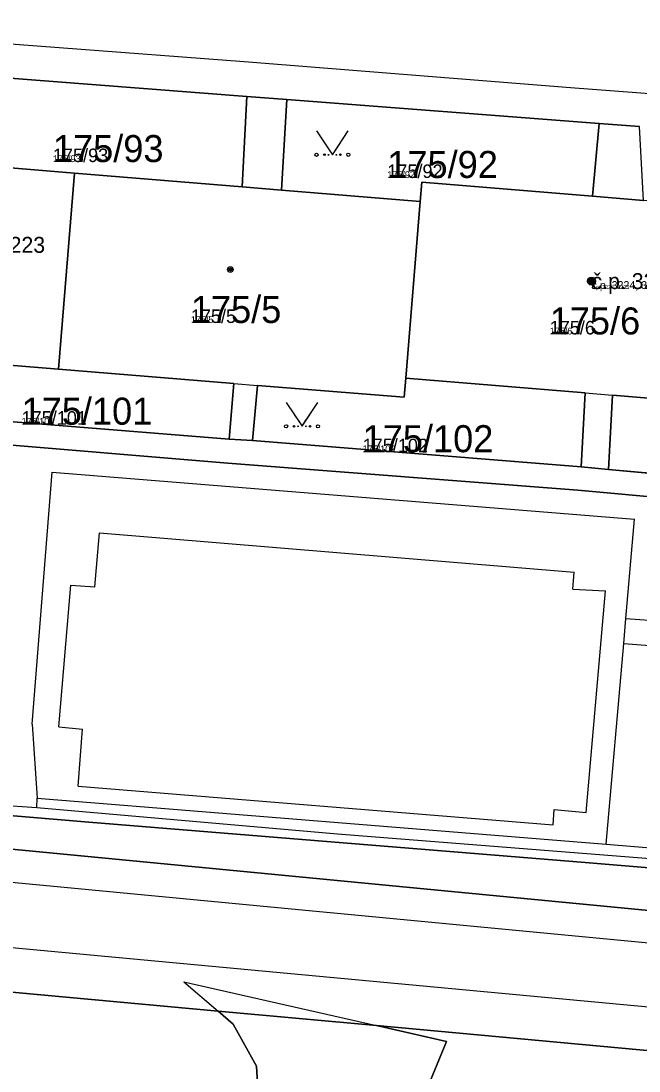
# Model space of a CAD drawing. Extents: x -759873 to -758487, y -975024 to -973516.
# Drawn here: x -759644.6 to -759605.8, y -974770.4 to -974704.4 of the extents above; entities that cross this region are included whole.
import ezdxf

# ---------------------------------------------------------------- set-up
doc = ezdxf.new("R2010")
doc.units = 0
for name, color, linetype in [('KAT_02_hranice parcel', 7, 'Continuous'), ('KAT_03_1000_st čísla parcelní', 7, 'Continuous'), ('KAT_03_1000_čísla parcelní', 7, 'Continuous'), ('KAT_03_1000_čísla popisná', 7, 'Continuous'), ('KAT_03_250_st čísla parcelní', 7, 'Continuous'), ('KAT_03_250_čísla parcelní', 7, 'Continuous'), ('KAT_03_250_čísla popisná', 7, 'Continuous'), ('KAT_03_500_st čísla parcelní', 7, 'Continuous'), ('KAT_03_500_čísla parcelní', 7, 'Continuous'), ('KAT_03_500_čísla popisná', 7, 'Continuous'), ('KAT_04_vnitřní kresba', 7, 'Continuous'), ('KAT_05_1000_značky kultur', 7, 'Continuous'), ('KAT_05_250_značky kultur', 7, 'Continuous'), ('KAT_05_500_značky kultur', 7, 'Continuous'), ('KAT_07_1000_značky budov', 7, 'Continuous'), ('KAT_07_250_značky budov', 7, 'Continuous'), ('KAT_07_500_značky budov', 7, 'Continuous'), ('KAT_14_plocha_budovy', 7, 'Continuous'), ('KAT_14_plocha_pozemek', 7, 'Continuous')]:
    doc.layers.add(name, color=color, linetype=linetype)

msp = doc.modelspace()

# ---------------------------------------------------------------- linework, layer by layer
at = {"layer": 'KAT_02_hranice parcel'}
for p, q in [((-759649.39, -974707.68), (-759630.43, -974709.14)), ((-759627.92, -974709.32), (-759630.43, -974709.14)), ((-759627.92, -974709.32), (-759608.29, -974710.84)), ((-759605.74, -974711.03), (-759608.29, -974710.84)), ((-759642.27, -974726.27), (-759641.27, -974713.96)), ((-759620.43, -974726.84), (-759619.53, -974715.73)), ((-759651.64, -974729.05), (-759631.54, -974730.66)), ((-759631.54, -974730.66), (-759630.08, -974730.75)), ((-759630.08, -974730.75), (-759609.42, -974732.4)), ((-759609.42, -974732.4), (-759607.69, -974732.58)), ((-759607.69, -974732.58), (-759588.03, -974734.34)), ((-759622.27, -974767.52), (-759632.24, -974766.61))]:
    msp.add_line(p, q, dxfattribs=at)
for points in [[(-759641.27, -974713.96), (-759649.11, -974713.31), (-759649.39, -974707.68)], [(-759630.43, -974709.14), (-759630.73, -974714.82), (-759641.27, -974713.96)], [(-759619.53, -974715.73), (-759628.26, -974715.02), (-759627.92, -974709.32)], [(-759608.29, -974710.84), (-759608.7, -974715.41), (-759619.43, -974714.53), (-759619.53, -974715.73)], [(-759651.64, -974729.05), (-759651.25, -974725.53), (-759642.27, -974726.27)], [(-759642.27, -974726.27), (-759631.25, -974727.17), (-759631.54, -974730.66)], [(-759630.08, -974730.75), (-759629.76, -974727.29), (-759620.53, -974728.04), (-759620.43, -974726.84)], [(-759620.43, -974726.84), (-759609.16, -974727.76), (-759609.42, -974732.4)], [(-759607.69, -974732.58), (-759607.44, -974727.9), (-759598.63, -974728.63)], [(-759647.22, -974730.88), (-759631.63, -974732.18), (-759609.62, -974733.88), (-759603.65, -974734.41), (-759602.12, -974734.54), (-759585.63, -974736), (-759581.26, -974735.71)], [(-759632.24, -974766.61), (-759693, -974761.02), (-759748.53, -974752.57), (-759765.29, -974749.94), (-759777.22, -974746.13)], [(-759717.74, -974748.2), (-759711.27, -974749.14), (-759692.25, -974751.9), (-759582.09, -974762.5), (-759499.92, -974767.02), (-759477.49, -974765.76)], [(-759560.6, -974761.29), (-759572.03, -974760.36), (-759609.16, -974757.26), (-759640.37, -974754.73), (-759646.11, -974754.26), (-759649.25, -974754), (-759649.17, -974753.04)], [(-759709.76, -974789.79), (-759694.52, -974791.11), (-759689.46, -974791.19), (-759651.79, -974790.02), (-759639.49, -974789.57), (-759635.49, -974788.88), (-759632.45, -974786.48), (-759630.15, -974781.17), (-759629.53, -974775.06), (-759629.82, -974770.06), (-759631.29, -974767.42), (-759632.24, -974766.61)], [(-759493.33, -974775.87), (-759498.32, -974775.83), (-759582.59, -974771.17), (-759622.27, -974767.52)], [(-759610.35, -974777.27), (-759613.56, -974776.84), (-759617.11, -974774.92), (-759619.06, -974771.36), (-759617.87, -974768.52), (-759622.27, -974767.52)]]:
    msp.add_lwpolyline(points, dxfattribs=at)
at = {"layer": 'KAT_03_1000_čísla popisná'}
msp.add_circle((-759608.76, -974720.74), 0.25, dxfattribs=at)
at = {"layer": 'KAT_03_250_čísla popisná'}
msp.add_circle((-759608.76, -974720.74), 0.0625, dxfattribs=at)
at = {"layer": 'KAT_03_500_čísla popisná'}
msp.add_circle((-759608.76, -974720.74), 0.125, dxfattribs=at)
at = {"layer": 'KAT_04_vnitřní kresba'}
for p, q in [((-759653.32, -974705.22), (-759630.6, -974706.95)), ((-759630.6, -974706.95), (-759610.08, -974708.57)), ((-759610.08, -974708.57), (-759591.35, -974710.02)), ((-759630.73, -974714.82), (-759628.26, -974715.02)), ((-759608.7, -974715.41), (-759605.49, -974715.67)), ((-759631.25, -974727.17), (-759629.76, -974727.29)), ((-759609.16, -974727.76), (-759607.44, -974727.9)), ((-759643.93, -974748.57), (-759642.67, -974732.75)), ((-759642.67, -974732.75), (-759606.05, -974735.69)), ((-759606.6, -974741.93), (-759606.05, -974735.69)), ((-759639.99, -974739.95), (-759639.7, -974736.55)), ((-759639.7, -974736.55), (-759609.85, -974739.03)), ((-759609.94, -974740.09), (-759609.85, -974739.03)), ((-759642.25, -974748.74), (-759641.5, -974739.85)), ((-759641.5, -974739.85), (-759639.99, -974739.95)), ((-759609.94, -974740.09), (-759607.89, -974740.2)), ((-759609.09, -974754.13), (-759607.89, -974740.2)), ((-759606.74, -974743.5), (-759606.6, -974741.93)), ((-759606.6, -974741.93), (-759604.26, -974742.11)), ((-759607.85, -974756.12), (-759606.74, -974743.5)), ((-759606.74, -974743.5), (-759604.06, -974743.71)), ((-759643.93, -974748.57), (-759643.6, -974753.23)), ((-759642.25, -974748.74), (-759640.75, -974748.9)), ((-759641.04, -974752.48), (-759640.75, -974748.9)), ((-759641.04, -974752.48), (-759611.18, -974754.91)), ((-759646.1, -974753.65), (-759643.64, -974753.81)), ((-759643.64, -974753.81), (-759643.6, -974753.23)), ((-759643.6, -974753.23), (-759607.85, -974756.12)), ((-759692.41, -974754), (-759582.2, -974764.5)), ((-759643.64, -974753.81), (-759624.72, -974755.47)), ((-759611.18, -974754.91), (-759611.1, -974753.94)), ((-759611.1, -974753.94), (-759609.09, -974754.13)), ((-759624.72, -974755.47), (-759588.82, -974758.29)), ((-759607.85, -974756.12), (-759560.5, -974759.95)), ((-759692.8, -974758.18), (-759582.51, -974768.44)), ((-759634.38, -974764.77), (-759632.24, -974766.61)), ((-759634.38, -974764.77), (-759622.27, -974767.52))]:
    msp.add_line(p, q, dxfattribs=at)
at = {"layer": 'KAT_05_1000_značky kultur'}
for points in [[(-759626.05, -974711.299), (-759625.05, -974712.8), (-759624.05, -974711.299)], [(-759627.96, -974728.359), (-759626.96, -974729.86), (-759625.96, -974728.359)]]:
    msp.add_lwpolyline(points, dxfattribs=at)
for centre in [(-759626.05, -974712.799), (-759624.05, -974712.799), (-759627.96, -974729.859), (-759625.96, -974729.859)]:
    msp.add_circle(centre, 0.1, dxfattribs=at)
at = {"layer": 'KAT_05_250_značky kultur'}
for points in [[(-759625.3, -974712.425), (-759625.05, -974712.8), (-759624.8, -974712.425)], [(-759627.21, -974729.485), (-759626.96, -974729.86), (-759626.71, -974729.485)]]:
    msp.add_lwpolyline(points, dxfattribs=at)
for centre in [(-759625.3, -974712.8), (-759624.8, -974712.8), (-759627.21, -974729.86), (-759626.71, -974729.86)]:
    msp.add_circle(centre, 0.025, dxfattribs=at)
at = {"layer": 'KAT_05_500_značky kultur'}
for points in [[(-759625.55, -974712.049), (-759625.05, -974712.8), (-759624.55, -974712.049)], [(-759627.46, -974729.11), (-759626.96, -974729.86), (-759626.46, -974729.11)]]:
    msp.add_lwpolyline(points, dxfattribs=at)
for centre in [(-759625.55, -974712.8), (-759624.55, -974712.8), (-759627.46, -974729.86), (-759626.46, -974729.86)]:
    msp.add_circle(centre, 0.05, dxfattribs=at)
at = {"layer": 'KAT_07_1000_značky budov'}
for centre in [(-759631.467, -974720.009), (-759608.767, -974720.739)]:
    msp.add_circle(centre, 0.175, dxfattribs=at)
at = {"layer": 'KAT_07_250_značky budov'}
for centre in [(-759631.462, -974720.01), (-759608.762, -974720.74)]:
    msp.add_circle(centre, 0.0437, dxfattribs=at)
at = {"layer": 'KAT_07_500_značky budov'}
for centre in [(-759631.463, -974720.01), (-759608.763, -974720.74)]:
    msp.add_circle(centre, 0.0875, dxfattribs=at)
at = {"layer": 'KAT_14_plocha_budovy'}
for points in [[(-759663.01, -974712.18), (-759664.01, -974724.49), (-759652.77, -974725.41), (-759651.25, -974725.53), (-759642.27, -974726.27), (-759631.25, -974727.17), (-759629.76, -974727.29), (-759620.53, -974728.04), (-759620.43, -974726.84), (-759619.53, -974715.73), (-759628.26, -974715.02), (-759630.73, -974714.82), (-759641.27, -974713.96), (-759649.11, -974713.31), (-759652.31, -974713.05)], [(-759620.43, -974726.84), (-759609.16, -974727.76), (-759607.44, -974727.9), (-759598.63, -974728.63), (-759587.58, -974729.53), (-759585.9, -974729.67), (-759576.84, -974730.41), (-759575.83, -974718.1), (-759584.58, -974717.38), (-759587.06, -974717.18), (-759597.63, -974716.32), (-759605.49, -974715.67), (-759608.7, -974715.41), (-759619.43, -974714.53), (-759619.53, -974715.73)]]:
    msp.add_lwpolyline(points, close=True, dxfattribs=at)
at = {"layer": 'KAT_14_plocha_pozemek'}
for points in [[(-759721.85, -974701.93), (-759712.7, -974702.91), (-759710.75, -974703.04), (-759695.32, -974704.11), (-759692.69, -974704.49), (-759673.78, -974705.9), (-759671.39, -974706.09), (-759651.83, -974707.5), (-759649.39, -974707.68), (-759630.43, -974709.14), (-759627.92, -974709.32), (-759608.29, -974710.84), (-759605.74, -974711.03)], [(-759588.03, -974734.34), (-759607.69, -974732.58), (-759609.42, -974732.4), (-759630.08, -974730.75), (-759631.54, -974730.66), (-759651.64, -974729.05), (-759653.14, -974728.9), (-759673.58, -974727.24), (-759675.02, -974727.09), (-759695.14, -974725.4), (-759696.95, -974725.28), (-759712.53, -974723.97), (-759710.75, -974703.04), (-759712.7, -974702.91), (-759713.04, -974706.66), (-759713.31, -974710.06), (-759713.45, -974711.78), (-759713.54, -974712.85), (-759714.48, -974723.81), (-759721.48, -974723.21)], [(-759721.81, -974724.63), (-759713.66, -974725.35), (-759696.72, -974726.85), (-759675.13, -974728.61), (-759653.29, -974730.38), (-759647.22, -974730.88), (-759631.63, -974732.18), (-759609.62, -974733.88), (-759603.65, -974734.41)], [(-759582.09, -974762.5), (-759692.25, -974751.9), (-759711.27, -974749.14), (-759717.74, -974748.2), (-759718.05, -974748.17), (-759724.35, -974747.51), (-759736.82, -974745.57), (-759738.11, -974745.25), (-759742.91, -974744.55), (-759749.66, -974743.57), (-759750.76, -974743.47), (-759752.97, -974743.27), (-759758.36, -974742.79), (-759763.29, -974742.35), (-759776.49, -974737.26), (-759776.57, -974738.23), (-759777.13, -974745.1), (-759777.22, -974746.13), (-759765.29, -974749.94), (-759748.53, -974752.57), (-759693, -974761.02), (-759632.24, -974766.61), (-759622.27, -974767.52), (-759582.59, -974771.17)], [(-759629.53, -974775.06), (-759629.82, -974770.06), (-759631.29, -974767.42), (-759632.24, -974766.61), (-759693, -974761.02), (-759748.53, -974752.57), (-759765.29, -974749.94), (-759777.22, -974746.13), (-759778.51, -974759.27), (-759779, -974768.63), (-759779.06, -974769.72), (-759779.44, -974777.04)], [(-759572.03, -974760.36), (-759609.16, -974757.26), (-759640.37, -974754.73), (-759646.11, -974754.26), (-759649.25, -974754), (-759649.17, -974753.04), (-759653.2, -974752.71), (-759653.28, -974753.71), (-759693.97, -974750.34), (-759709.81, -974749.04), (-759717.74, -974748.2), (-759711.27, -974749.14), (-759692.25, -974751.9), (-759582.09, -974762.5)], [(-759619.06, -974771.36), (-759617.87, -974768.52), (-759622.27, -974767.52), (-759632.24, -974766.61), (-759631.29, -974767.42), (-759629.82, -974770.06), (-759629.53, -974775.06)]]:
    msp.add_lwpolyline(points, dxfattribs=at)
for points in [[(-759651.25, -974725.53), (-759642.27, -974726.27), (-759641.27, -974713.96), (-759649.11, -974713.31), (-759649.39, -974707.68), (-759651.83, -974707.5), (-759652.31, -974713.05), (-759663.01, -974712.18), (-759664.01, -974724.49), (-759652.77, -974725.41), (-759653.14, -974728.9), (-759651.64, -974729.05)], [(-759649.39, -974707.68), (-759649.11, -974713.31), (-759641.27, -974713.96), (-759630.73, -974714.82), (-759630.43, -974709.14)], [(-759631.25, -974727.17), (-759631.54, -974730.66), (-759630.08, -974730.75), (-759629.76, -974727.29), (-759620.53, -974728.04), (-759620.43, -974726.84), (-759619.53, -974715.73), (-759628.26, -974715.02), (-759627.92, -974709.32), (-759630.43, -974709.14), (-759630.73, -974714.82), (-759641.27, -974713.96), (-759642.27, -974726.27)], [(-759627.92, -974709.32), (-759628.26, -974715.02), (-759619.53, -974715.73), (-759619.43, -974714.53), (-759608.7, -974715.41), (-759608.29, -974710.84)], [(-759609.16, -974727.76), (-759609.42, -974732.4), (-759607.69, -974732.58), (-759607.44, -974727.9), (-759598.63, -974728.63), (-759597.63, -974716.32), (-759605.49, -974715.67), (-759605.74, -974711.03), (-759608.29, -974710.84), (-759608.7, -974715.41), (-759619.43, -974714.53), (-759619.53, -974715.73), (-759620.43, -974726.84)], [(-759631.54, -974730.66), (-759631.25, -974727.17), (-759642.27, -974726.27), (-759651.25, -974725.53), (-759651.64, -974729.05)], [(-759609.42, -974732.4), (-759609.16, -974727.76), (-759620.43, -974726.84), (-759620.53, -974728.04), (-759629.76, -974727.29), (-759630.08, -974730.75)], [(-759588.03, -974734.34), (-759587.58, -974729.53), (-759598.63, -974728.63), (-759607.44, -974727.9), (-759607.69, -974732.58)], [(-759560.55, -974760.58), (-759560.5, -974759.95), (-759560.36, -974758.15), (-759559.43, -974745.94), (-759559.31, -974744.32), (-759554.53, -974744.73), (-759554.44, -974743.54), (-759579.98, -974738.48), (-759581.47, -974738.34), (-759581.26, -974735.71), (-759585.63, -974736), (-759602.12, -974734.54), (-759603.65, -974734.41), (-759609.62, -974733.88), (-759631.63, -974732.18), (-759647.22, -974730.88), (-759647.39, -974732.84), (-759649.17, -974753.04), (-759649.25, -974754), (-759646.11, -974754.26), (-759640.37, -974754.73), (-759609.16, -974757.26), (-759572.03, -974760.36), (-759560.6, -974761.29)], [(-759493.33, -974775.87), (-759498.32, -974775.83), (-759582.59, -974771.17), (-759622.27, -974767.52), (-759617.87, -974768.52), (-759619.06, -974771.36), (-759617.11, -974774.92), (-759613.56, -974776.84), (-759610.35, -974777.27), (-759609.95, -974772.38), (-759572.8, -974775.33), (-759541.75, -974777.79), (-759500.3, -974781.07), (-759500.61, -974785.93), (-759495.44, -974785.77), (-759491.14, -974783.19), (-759489.31, -974781.1), (-759489.41, -974779.52), (-759492.24, -974776.63)]]:
    msp.add_lwpolyline(points, close=True, dxfattribs=at)

# ---------------------------------------------------------------- texts
at = {"layer": 'KAT_03_1000_st čísla parcelní'}
for s, p in [('175/5', (-759633.95, -974723.37)), ('175/6', (-759611.39, -974724.09))]:
    msp.add_text(s, height=1.7, dxfattribs=at).set_placement(p)
at = {"layer": 'KAT_03_1000_čísla parcelní'}
for s, p in [('175/93', (-759642.62, -974713.26)), ('175/92', (-759621.6, -974714.26)), ('175/101', (-759644.59, -974729.76)), ('175/102', (-759623.15, -974731.49))]:
    msp.add_text(s, height=1.7, dxfattribs=at).set_placement(p)
at = {"layer": 'KAT_03_1000_čísla popisná'}
for s, p in [('č.p. 3222, 3223', (-759652.33, -974718.96)), ('č.p. 3224, 3225', (-759608.76, -974721.24))]:
    msp.add_text(s, height=1, dxfattribs=at).set_placement(p)
at = {"layer": 'KAT_03_250_st čísla parcelní'}
for s, p in [('175/5', (-759633.95, -974723.37)), ('175/6', (-759611.39, -974724.09))]:
    msp.add_text(s, height=0.425, dxfattribs=at).set_placement(p)
at = {"layer": 'KAT_03_250_čísla parcelní'}
for s, p in [('175/93', (-759642.62, -974713.26)), ('175/92', (-759621.6, -974714.26)), ('175/101', (-759644.59, -974729.76)), ('175/102', (-759623.15, -974731.49))]:
    msp.add_text(s, height=0.425, dxfattribs=at).set_placement(p)
at = {"layer": 'KAT_03_250_čísla popisná'}
msp.add_text('č.p. 3224, 3225', height=0.25, dxfattribs=at).set_placement((-759608.76, -974721.24))
at = {"layer": 'KAT_03_500_st čísla parcelní'}
for s, p in [('175/5', (-759633.95, -974723.37)), ('175/6', (-759611.39, -974724.09))]:
    msp.add_text(s, height=0.85, dxfattribs=at).set_placement(p)
at = {"layer": 'KAT_03_500_čísla parcelní'}
for s, p in [('175/93', (-759642.62, -974713.26)), ('175/92', (-759621.6, -974714.26)), ('175/101', (-759644.59, -974729.76)), ('175/102', (-759623.15, -974731.49))]:
    msp.add_text(s, height=0.85, dxfattribs=at).set_placement(p)
at = {"layer": 'KAT_03_500_čísla popisná'}
msp.add_text('č.p. 3224, 3225', height=0.5, dxfattribs=at).set_placement((-759608.76, -974721.24))

doc.saveas('drawing.dxf')
